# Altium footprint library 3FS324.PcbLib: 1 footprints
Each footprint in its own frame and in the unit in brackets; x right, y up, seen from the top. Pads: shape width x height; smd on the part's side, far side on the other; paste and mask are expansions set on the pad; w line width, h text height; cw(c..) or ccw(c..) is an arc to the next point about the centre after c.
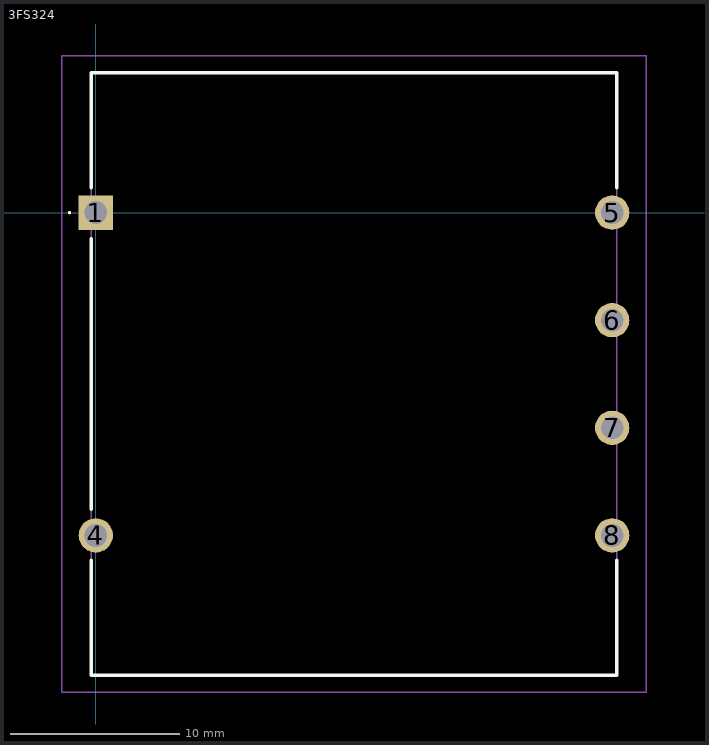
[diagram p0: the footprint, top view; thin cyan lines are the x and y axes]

## 3FS324 [mm]
pads (6):
  rect 2.025x2.025 hole 1.35: 1(0,0)
  round 2.025 hole 1.35: 4(0,-19.05) 5(30.48,0) 6(30.48,-6.35) 7(30.48,-12.7) 8(30.48,-19.05)
Top Overlay:
  lines w0.1: -1.6,0 cw(c-1.55,0) -1.5,0 ; -1.6,0 -1.6,0 ; -1.6,0 ccw(c-1.55,0) -1.5,0 ; -1.5,0 -1.5,0
  lines w0.2: -0.26,-20.525 -0.26,-27.305 30.74,-27.305 30.74,-20.525 ; -0.26,-17.525 -0.26,-1.525 ; -0.26,1.475 -0.26,8.255 30.74,8.255 30.74,1.475
Mechanical 15:
  lines w0.1: -0.26,-27.305 30.74,-27.305 30.74,8.255 -0.26,8.255 -0.26,-27.305
Mechanical 20:
  lines w0.1: -2.013,-28.305 32.492,-28.305 32.492,9.255 -2.013,9.255 -2.013,-28.305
